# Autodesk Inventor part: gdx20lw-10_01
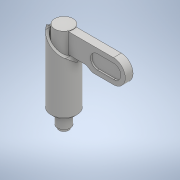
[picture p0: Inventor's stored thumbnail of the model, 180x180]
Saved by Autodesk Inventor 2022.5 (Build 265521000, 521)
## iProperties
Part Number: gdx20lw-10_01
Material: 一般
Document SubType Name: Modeling
Designer: ImaoCorp
Density: 1 g/cm^3
Appearance: 既定
Author: ImaoCorp
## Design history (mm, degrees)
feature "gdx20lw-10_01"
node "ソリッド1"
